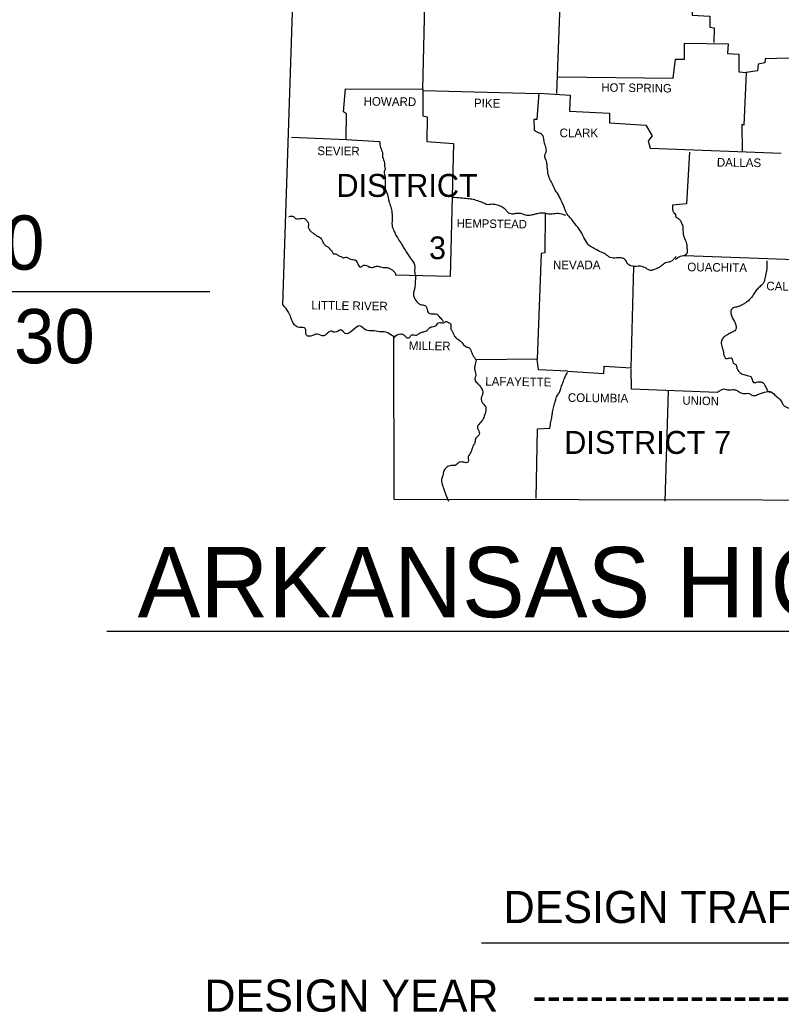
# Model space of a CAD drawing. Extents: x 1196286 to 1268366, y 2040822 to 2082115.
# Drawn here: x 1243666 to 1251238, y 2061907 to 2071784 of the extents above; entities that cross this region are included whole.
import ezdxf

# ---------------------------------------------------------------- set-up
doc = ezdxf.new("R2010")
doc.units = 0
for name, color, linetype in [('21', 7, 'Continuous'), ('60', 7, 'Continuous'), ('Level 8', 7, 'Continuous')]:
    doc.layers.add(name, color=color, linetype=linetype)

msp = doc.modelspace()

# ---------------------------------------------------------------- linework, layer by layer
at = {"layer": 'Level 8'}
for p, q in [((1245554.7, 2069077.4), (1238412.5, 2069077.4)), ((1244531.4, 2065699.7), (1257755.9, 2065699.7)), ((1248081.4, 2062954), (1248081.4, 2062954)), ((1248259.2, 2062598.4), (1253948, 2062598.4))]:
    msp.add_line(p, q, dxfattribs=at)
for points in [[(1246280.3, 2068949.7), (1246460.3, 2074375.7), (1246046.3, 2077699.7)], [(1249006.3, 2071051.7), (1249052.3, 2072297.7)], [(1249880.3, 2072375.7), (1250122.3, 2072357.7), (1250130.3, 2072105.7), (1250096.3, 2072093.7), (1250092.3, 2071959.7), (1250354.3, 2071941.7), (1250354.3, 2071831.7), (1250528.3, 2071821.7), (1250530.3, 2071711.7), (1250572.3, 2071705.7), (1250570.3, 2071557.7)], [(1246366.3, 2070615.7), (1246912.3, 2070591.7), (1246914.3, 2070847.7), (1246886.3, 2070867.7), (1246904.3, 2071095.7), (1247674.3, 2071093.7), (1247696.3, 2072077.7)], [(1249020.3, 2071217.7), (1250164.3, 2071201.7), (1250186.3, 2071391.7), (1250276.3, 2071391.7), (1250278.3, 2071551.7), (1250710.3, 2071545.7), (1250706.3, 2071449.7), (1250818.3, 2071441.7), (1250818.3, 2071265.7), (1250890.3, 2071259.7)], [(1252042.3, 2071523.7), (1251564.3, 2071531.7), (1251546.3, 2071409.7), (1251080.3, 2071395.7), (1251076.3, 2071355.7), (1251010.3, 2071343.7), (1251002.3, 2071275.7), (1250890.3, 2071259.7)], [(1250890.3, 2071259.7), (1250866.3, 2070735.7), (1250848.3, 2070741.7), (1250850.3, 2070469.7)], [(1247674.3, 2071093.7), (1247674.3, 2070827.7), (1247718.3, 2070819.7), (1247714.3, 2070571.7), (1247978.3, 2070551.7), (1247946.3, 2069229.7), (1247402.3, 2069243.7)], [(1247678.3, 2071079.7), (1248822.3, 2071049.7)], [(1248784.3, 2070683.7), (1248780.3, 2070793.7), (1248812.3, 2070795.7), (1248832.3, 2071053.7), (1249140.3, 2071033.7), (1249132.3, 2070875.7), (1249530.3, 2070853.7), (1249532.3, 2070757.7), (1249892.3, 2070735.7), (1249954.3, 2070627.7), (1249916.3, 2070579.7), (1249934.3, 2070505.7), (1251238.3, 2070457.7)], [(1246912.3, 2070591.7), (1247244.3, 2070571.7)], [(1250326.3, 2070467.7), (1250296.3, 2069953.7), (1250158.3, 2069937.7)], [(1248890.3, 2069861.7), (1248886.3, 2069463.7), (1248850.3, 2069459.7), (1248810.3, 2068405.7)], [(1250276.3, 2069439.7), (1251104.3, 2069409.7), (1251718.3, 2069385.7)], [(1249114.3, 2068285.7), (1249474.3, 2068263.7), (1249476.3, 2068337.7), (1249746.3, 2068319.7), (1249772.3, 2069327.7)], [(1254720.3, 2066997.7), (1247390.3, 2067009.7), (1247386.3, 2068627.7)], [(1249114.3, 2068285.7), (1248824.3, 2068301.7), (1248810.3, 2068405.7), (1248204.3, 2068399.7)], [(1250604.3, 2068075.7), (1249750.3, 2068107.7), (1249746.3, 2068309.7)], [(1250114.3, 2068089.7), (1250082.3, 2066991.7)], [(1248800.3, 2067019.7), (1248814.3, 2067711.7), (1248938.3, 2067719.7)]]:
    msp.add_lwpolyline(points, dxfattribs=at)
for points in [[(1249772.3, 2069327.7), (1249744.3, 2069335.7), (1249708.3, 2069359.7), (1249688.3, 2069395.7), (1249646.3, 2069413.7), (1249600.3, 2069413.7), (1249538.3, 2069417.7), (1249490.3, 2069451.7), (1249448.3, 2069471.7), (1249382.3, 2069505.7), (1249330.3, 2069537.7), (1249284.3, 2069601.7), (1249254.3, 2069659.7), (1249200.3, 2069737.7), (1249140.3, 2069813.7), (1249102.3, 2069863.7), (1249072.3, 2069937.7), (1249056.3, 2069973.7), (1249022.3, 2070041.7), (1248982.3, 2070103.7), (1248958.3, 2070161.7), (1248932.3, 2070209.7), (1248916.3, 2070279.7), (1248910.3, 2070331.7), (1248904.3, 2070375.7), (1248888.3, 2070439.7), (1248900.3, 2070467.7), (1248896.3, 2070519.7), (1248882.3, 2070569.7), (1248874.3, 2070615.7), (1248854.3, 2070645.7), (1248816.3, 2070663.7), (1248784.3, 2070683.7)], [(1247244.3, 2070571.7), (1247254.3, 2070511.7), (1247272.3, 2070459.7), (1247274.3, 2070419.7), (1247292.3, 2070359.7), (1247292.3, 2070337.7), (1247298.3, 2070293.7), (1247290.3, 2070269.7), (1247300.3, 2070221.7), (1247298.3, 2070185.7), (1247298.3, 2070155.7), (1247300.3, 2070105.7), (1247316.3, 2070061.7), (1247332.3, 2069995.7), (1247342.3, 2069961.7), (1247358.3, 2069909.7), (1247368.3, 2069845.7), (1247370.3, 2069797.7), (1247366.3, 2069753.7), (1247378.3, 2069703.7), (1247400.3, 2069653.7), (1247428.3, 2069605.7), (1247462.3, 2069551.7), (1247486.3, 2069509.7), (1247516.3, 2069463.7), (1247540.3, 2069425.7), (1247576.3, 2069377.7), (1247592.3, 2069337.7), (1247592.3, 2069281.7), (1247600.3, 2069229.7), (1247598.3, 2069171.7), (1247594.3, 2069119.7), (1247580.3, 2069047.7), (1247590.3, 2069013.7), (1247628.3, 2068963.7), (1247652.3, 2068949.7), (1247694.3, 2068941.7), (1247714.3, 2068913.7), (1247726.3, 2068871.7), (1247768.3, 2068857.7), (1247814.3, 2068853.7), (1247836.3, 2068829.7), (1247866.3, 2068797.7), (1247876.3, 2068781.7)], [(1247974.3, 2070019.7), (1248050.3, 2070013.7), (1248120.3, 2070005.7), (1248174.3, 2069999.7), (1248230.3, 2069979.7), (1248280.3, 2069961.7), (1248312.3, 2069947.7), (1248366.3, 2069951.7), (1248412.3, 2069941.7), (1248464.3, 2069923.7), (1248502.3, 2069889.7), (1248526.3, 2069863.7), (1248572.3, 2069853.7), (1248610.3, 2069859.7), (1248656.3, 2069855.7), (1248708.3, 2069839.7), (1248750.3, 2069841.7), (1248784.3, 2069849.7), (1248824.3, 2069859.7), (1248874.3, 2069863.7), (1248912.3, 2069855.7), (1248962.3, 2069853.7), (1249020.3, 2069859.7), (1249092.3, 2069839.7)], [(1250158.3, 2069937.7), (1250158.3, 2069899.7), (1250172.3, 2069863.7), (1250186.3, 2069847.7), (1250192.3, 2069821.7), (1250210.3, 2069809.7), (1250236.3, 2069785.7), (1250250.3, 2069751.7), (1250260.3, 2069729.7), (1250260.3, 2069701.7), (1250262.3, 2069673.7), (1250266.3, 2069639.7), (1250290.3, 2069579.7), (1250296.3, 2069555.7), (1250300.3, 2069535.7), (1250302.3, 2069501.7), (1250302.3, 2069461.7), (1250276.3, 2069439.7)], [(1246342.3, 2069825.7), (1246386.3, 2069827.7), (1246416.3, 2069801.7), (1246434.3, 2069803.7), (1246466.3, 2069807.7), (1246496.3, 2069805.7), (1246518.3, 2069787.7), (1246536.3, 2069755.7), (1246534.3, 2069725.7), (1246536.3, 2069713.7), (1246550.3, 2069687.7), (1246574.3, 2069667.7), (1246600.3, 2069647.7), (1246624.3, 2069631.7), (1246664.3, 2069605.7), (1246668.3, 2069597.7), (1246684.3, 2069565.7), (1246704.3, 2069539.7), (1246728.3, 2069523.7), (1246754.3, 2069495.7), (1246766.3, 2069483.7), (1246786.3, 2069455.7), (1246808.3, 2069453.7), (1246838.3, 2069435.7), (1246860.3, 2069429.7), (1246884.3, 2069413.7), (1246908.3, 2069421.7), (1246938.3, 2069409.7), (1246978.3, 2069397.7), (1247000.3, 2069393.7), (1247026.3, 2069355.7), (1247052.3, 2069323.7), (1247084.3, 2069341.7), (1247144.3, 2069323.7), (1247182.3, 2069321.7), (1247216.3, 2069331.7), (1247242.3, 2069329.7), (1247290.3, 2069317.7), (1247320.3, 2069317.7), (1247352.3, 2069305.7), (1247382.3, 2069281.7), (1247402.3, 2069255.7), (1247402.3, 2069243.7)], [(1250194.3, 2069429.7), (1250172.3, 2069403.7), (1250146.3, 2069381.7), (1250116.3, 2069371.7), (1250088.3, 2069363.7), (1250052.3, 2069339.7), (1250024.3, 2069319.7), (1249986.3, 2069301.7), (1249950.3, 2069289.7), (1249906.3, 2069303.7), (1249882.3, 2069317.7), (1249856.3, 2069327.7), (1249772.3, 2069327.7)], [(1250186.3, 2069397.7), (1250238.3, 2069431.7), (1250296.3, 2069439.7)], [(1251096.3, 2069385.7), (1251092.3, 2069285.7), (1251078.3, 2069223.7), (1251064.3, 2069167.7), (1251034.3, 2069135.7), (1251002.3, 2069103.7), (1250972.3, 2069067.7), (1250946.3, 2069023.7), (1250920.3, 2068995.7), (1250886.3, 2068967.7), (1250852.3, 2068947.7), (1250814.3, 2068929.7), (1250772.3, 2068919.7), (1250742.3, 2068897.7), (1250740.3, 2068849.7), (1250774.3, 2068781.7), (1250786.3, 2068749.7), (1250790.3, 2068711.7), (1250776.3, 2068689.7), (1250744.3, 2068671.7), (1250706.3, 2068649.7), (1250672.3, 2068629.7), (1250648.3, 2068595.7), (1250644.3, 2068549.7), (1250660.3, 2068495.7), (1250666.3, 2068463.7), (1250692.3, 2068413.7), (1250712.3, 2068415.7), (1250748.3, 2068413.7), (1250752.3, 2068403.7), (1250754.3, 2068393.7), (1250762.3, 2068367.7), (1250792.3, 2068345.7), (1250796.3, 2068325.7), (1250814.3, 2068287.7), (1250844.3, 2068261.7), (1250866.3, 2068253.7), (1250912.3, 2068239.7), (1250936.3, 2068233.7), (1250962.3, 2068175.7), (1250994.3, 2068177.7), (1251018.3, 2068181.7), (1251058.3, 2068171.7), (1251076.3, 2068147.7), (1251094.3, 2068107.7), (1251118.3, 2068079.7), (1251134.3, 2068079.7)], [(1247386.3, 2068627.7), (1247394.3, 2068623.7), (1247356.3, 2068649.7), (1247304.3, 2068675.7), (1247246.3, 2068679.7), (1247172.3, 2068689.7), (1247110.3, 2068695.7), (1247046.3, 2068737.7), (1246978.3, 2068693.7), (1246902.3, 2068661.7), (1246858.3, 2068697.7), (1246800.3, 2068673.7), (1246760.3, 2068685.7), (1246690.3, 2068637.7), (1246624.3, 2068655.7), (1246576.3, 2068641.7), (1246516.3, 2068643.7), (1246504.3, 2068711.7), (1246446.3, 2068721.7), (1246396.3, 2068749.7), (1246362.3, 2068819.7), (1246338.3, 2068873.7), (1246280.3, 2068949.7)], [(1247386.3, 2068627.7), (1247456.3, 2068657.7), (1247486.3, 2068647.7), (1247512.3, 2068621.7), (1247542.3, 2068621.7), (1247558.3, 2068645.7), (1247588.3, 2068647.7), (1247612.3, 2068645.7), (1247638.3, 2068661.7), (1247660.3, 2068671.7), (1247690.3, 2068681.7), (1247712.3, 2068689.7), (1247732.3, 2068711.7), (1247768.3, 2068729.7), (1247810.3, 2068743.7), (1247822.3, 2068763.7), (1247842.3, 2068771.7), (1247882.3, 2068769.7), (1247908.3, 2068781.7), (1247930.3, 2068771.7), (1247950.3, 2068757.7), (1247954.3, 2068705.7), (1247970.3, 2068677.7), (1247994.3, 2068627.7), (1248028.3, 2068601.7), (1248060.3, 2068575.7), (1248072.3, 2068559.7), (1248106.3, 2068529.7), (1248136.3, 2068519.7), (1248150.3, 2068497.7), (1248172.3, 2068445.7), (1248204.3, 2068399.7)], [(1248204.3, 2068399.7), (1248192.3, 2068341.7), (1248190.3, 2068295.7), (1248200.3, 2068241.7), (1248190.3, 2068215.7), (1248206.3, 2068177.7), (1248236.3, 2068147.7), (1248258.3, 2068115.7), (1248272.3, 2068069.7), (1248254.3, 2068017.7), (1248274.3, 2067963.7), (1248292.3, 2067943.7), (1248302.3, 2067911.7), (1248288.3, 2067849.7), (1248270.3, 2067803.7), (1248230.3, 2067757.7), (1248218.3, 2067735.7), (1248224.3, 2067705.7), (1248234.3, 2067657.7), (1248224.3, 2067643.7), (1248198.3, 2067609.7), (1248190.3, 2067571.7), (1248172.3, 2067539.7), (1248152.3, 2067481.7), (1248126.3, 2067433.7), (1248122.3, 2067379.7), (1248082.3, 2067379.7), (1248036.3, 2067379.7), (1247994.3, 2067349.7), (1247956.3, 2067347.7), (1247910.3, 2067329.7), (1247882.3, 2067291.7), (1247872.3, 2067249.7), (1247860.3, 2067209.7), (1247872.3, 2067141.7), (1247890.3, 2067093.7), (1247904.3, 2067055.7), (1247928.3, 2066993.7)], [(1248938.3, 2067719.7), (1248948.3, 2067783.7), (1248958.3, 2067833.7), (1248964.3, 2067881.7), (1248976.3, 2067935.7), (1248994.3, 2067993.7), (1249010.3, 2068041.7), (1249032.3, 2068075.7), (1249046.3, 2068115.7), (1249064.3, 2068163.7), (1249082.3, 2068213.7), (1249114.3, 2068277.7)], [(1250604.3, 2068075.7), (1250636.3, 2068097.7), (1250666.3, 2068109.7), (1250696.3, 2068103.7), (1250728.3, 2068099.7), (1250756.3, 2068103.7), (1250792.3, 2068097.7), (1250822.3, 2068079.7), (1250856.3, 2068065.7), (1250890.3, 2068065.7), (1250920.3, 2068065.7), (1250946.3, 2068047.7), (1250994.3, 2068049.7), (1251034.3, 2068065.7), (1251074.3, 2068077.7), (1251128.3, 2068083.7), (1251176.3, 2068049.7), (1251210.3, 2068021.7), (1251238.3, 2067989.7), (1251258.3, 2067953.7), (1251280.3, 2067933.7), (1251316.3, 2067919.7), (1251344.3, 2067913.7), (1251378.3, 2067903.7), (1251396.3, 2067895.7), (1251412.3, 2067857.7), (1251438.3, 2067805.7), (1251488.3, 2067787.7), (1251550.3, 2067811.7), (1251600.3, 2067825.7), (1251636.3, 2067837.7), (1251658.3, 2067845.7), (1251678.3, 2067847.7), (1251672.3, 2067851.7), (1251696.3, 2067857.7), (1251718.3, 2067841.7), (1251732.3, 2067819.7), (1251756.3, 2067787.7), (1251778.3, 2067759.7), (1251800.3, 2067749.7), (1251822.3, 2067761.7), (1251852.3, 2067751.7), (1251878.3, 2067741.7), (1251908.3, 2067733.7), (1251934.3, 2067731.7), (1251968.3, 2067723.7), (1251994.3, 2067709.7), (1252018.3, 2067695.7), (1252042.3, 2067669.7), (1252066.3, 2067629.7), (1252074.3, 2067597.7), (1252102.3, 2067565.7), (1252128.3, 2067565.7), (1252166.3, 2067513.7), (1252180.3, 2067493.7), (1252210.3, 2067457.7), (1252232.3, 2067457.7), (1252274.3, 2067449.7)]]:
    msp.add_spline(points, degree=3, dxfattribs=at)

# ---------------------------------------------------------------- texts
at = {"layer": '21'}
msp.add_text('PIKE', height=85.99, rotation=359.04516, dxfattribs=at).set_placement((1248182.3, 2070913.7))
for s, height, p in [('DISTRICT', 228, (1246814.3, 2070021.7)), ('3', 226, (1247736.3, 2069401.7)), ('DISTRICT 7', 228, (1249080.3, 2067463.7))]:
    msp.add_text(s, height=height, dxfattribs=at).set_placement(p)
at = {"layer": '60'}
for s, height, rotation, p in [('HOT SPRING', 84.01, 359.22157, (1249450.3, 2071069.7)), ('HOWARD', 86.02, 359.51446, (1247084.3, 2070929.7)), ('SEVIER', 86.02, 359.42706, (1246624.3, 2070437.7)), ('DALLAS', 85.99, 359.24615, (1250598.3, 2070323.7)), ('HEMPSTEAD', 83.99, 359.1885, (1248010.3, 2069717.7)), ('OUACHITA', 86.02, 359.20428, (1250304.3, 2069281.7)), ('CALHOUN', 86.02, 359.36341, (1251090.3, 2069091.7)), ('LITTLE RIVER', 86.016, 359.16968, (1246564.3, 2068901.7)), ('MILLER', 85.99, 359.13195, (1247534.3, 2068499.7)), ('LAFAYETTE', 85.99, 359.18388, (1248294.3, 2068143.7)), ('COLUMBIA', 85.99, 359.21248, (1249116.3, 2067981.7)), ('UNION', 84.01, 358.95837, (1250256.3, 2067953.7))]:
    msp.add_text(s, height=height, rotation=rotation, dxfattribs=at).set_placement(p)
for s, height, p in [('CLARK', 86, (1249034.3, 2070615.7)), ('STA. 465+40.00', 540, (1238671.3, 2069297.1)), ('NEVADA', 86, (1248968.3, 2069301.7)), ('END JOB 020630', 540, (1238671.3, 2068365.3)), ('ARKANSAS HIGHWAY DISTRICT 2', 700, (1244837.7, 2065837.7)), ('DESIGN YEAR', 320, (1245501.7, 2061911.8)), ('-----------------------', 320, (1248763.1, 2061911.8))]:
    msp.add_text(s, height=height, dxfattribs=at).set_placement(p)
at = {"layer": 'Level 8'}
msp.add_text('DESIGN TRAFFIC DATA', height=320, dxfattribs=at).set_placement((1248477.8, 2062794))

doc.saveas('drawing.dxf')
